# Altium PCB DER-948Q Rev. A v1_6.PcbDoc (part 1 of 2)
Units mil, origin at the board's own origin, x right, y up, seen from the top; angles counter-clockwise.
Board outline 4950 x 2915 mil, 6 copper layers (Top Layer, Mid-Layer 1, Mid-Layer 2, Mid-Layer 3, Mid-Layer 4, Bottom Layer), stack 69.8 mil thick; 98 components, 37 nets, 247 pads, 846 vias.
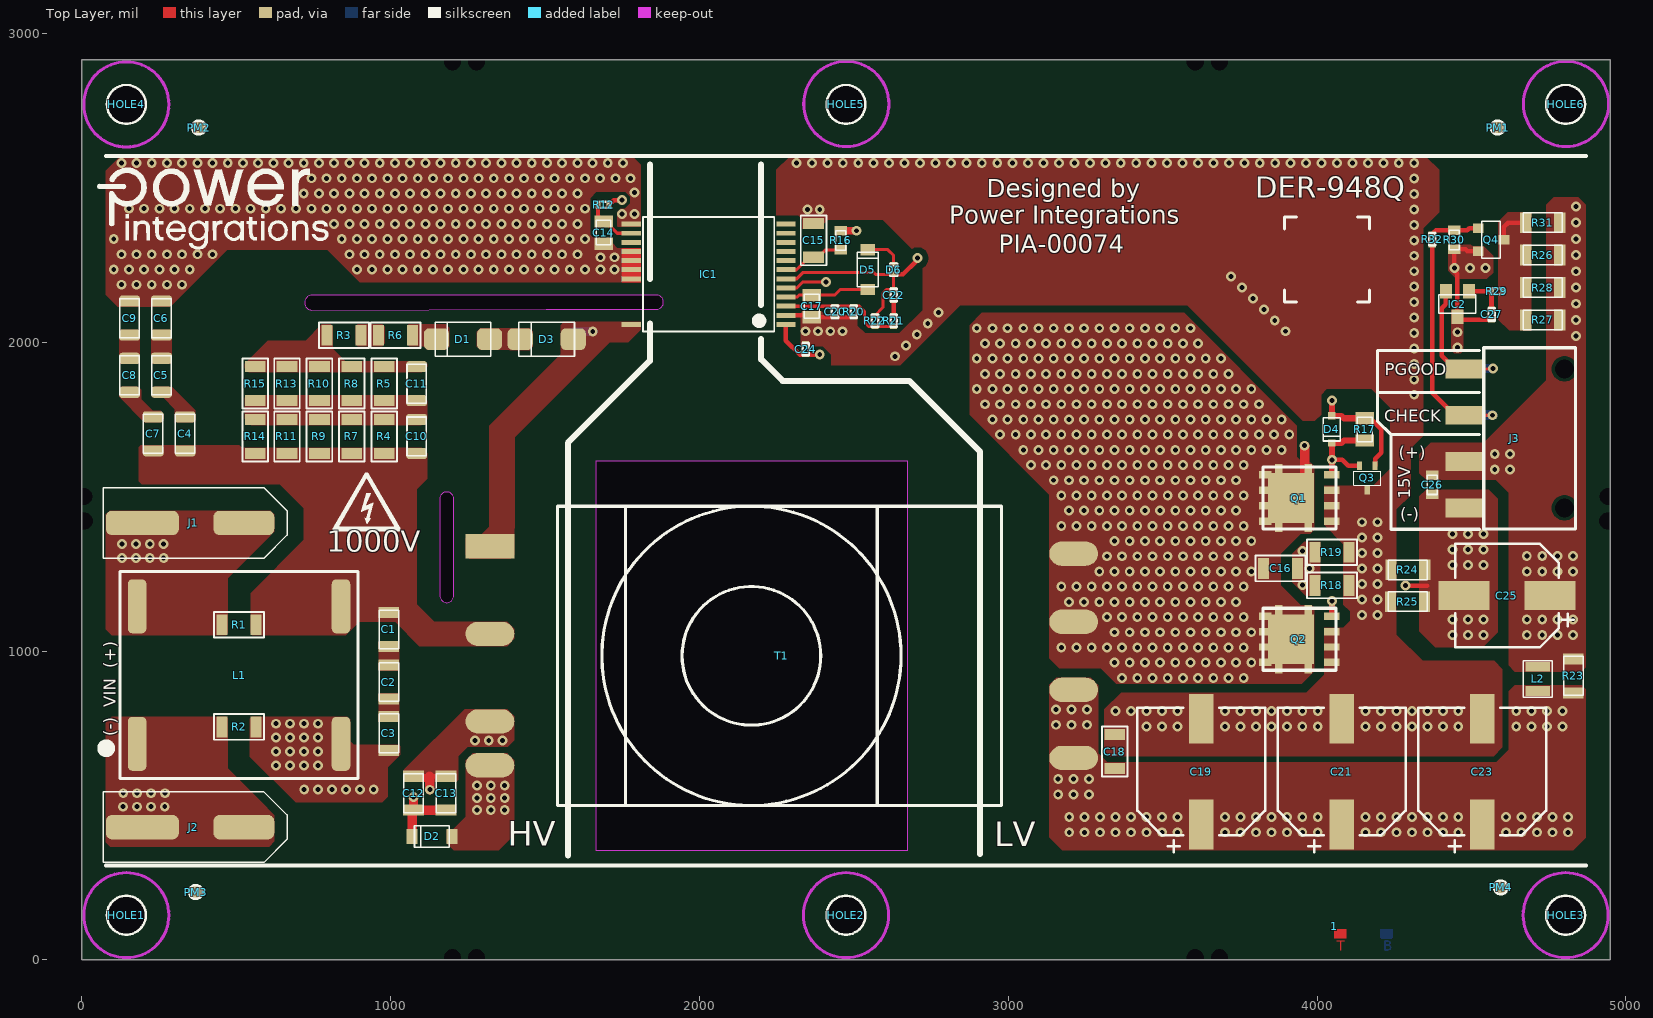
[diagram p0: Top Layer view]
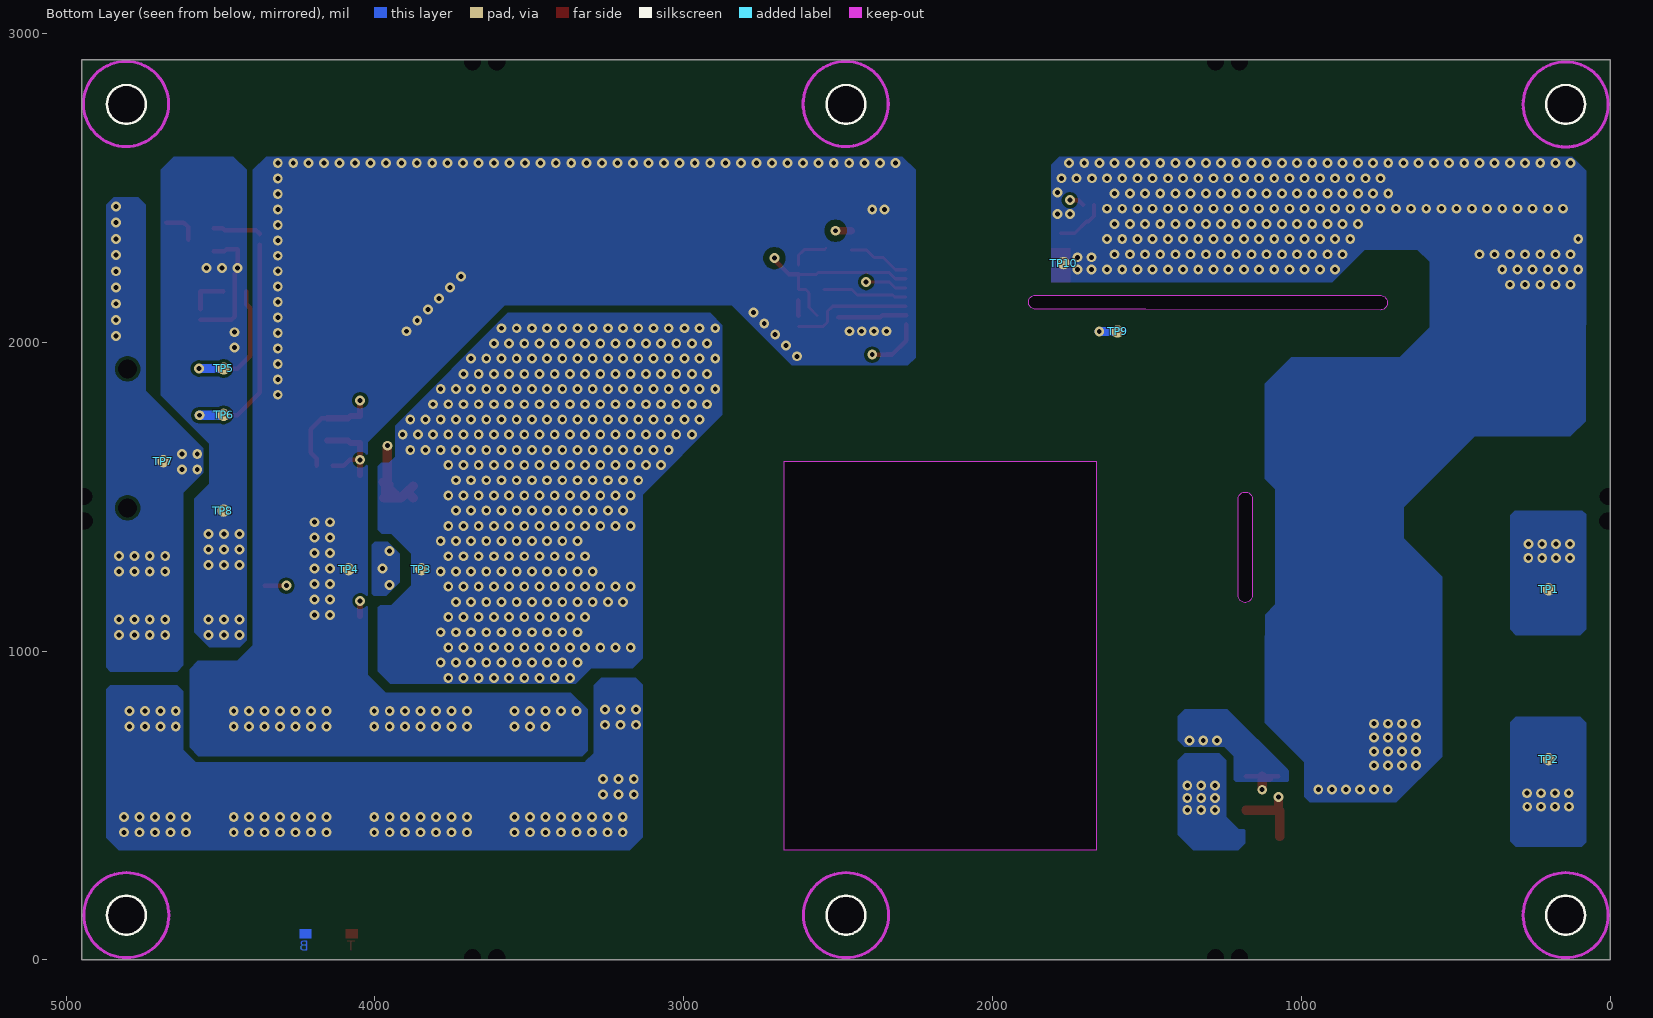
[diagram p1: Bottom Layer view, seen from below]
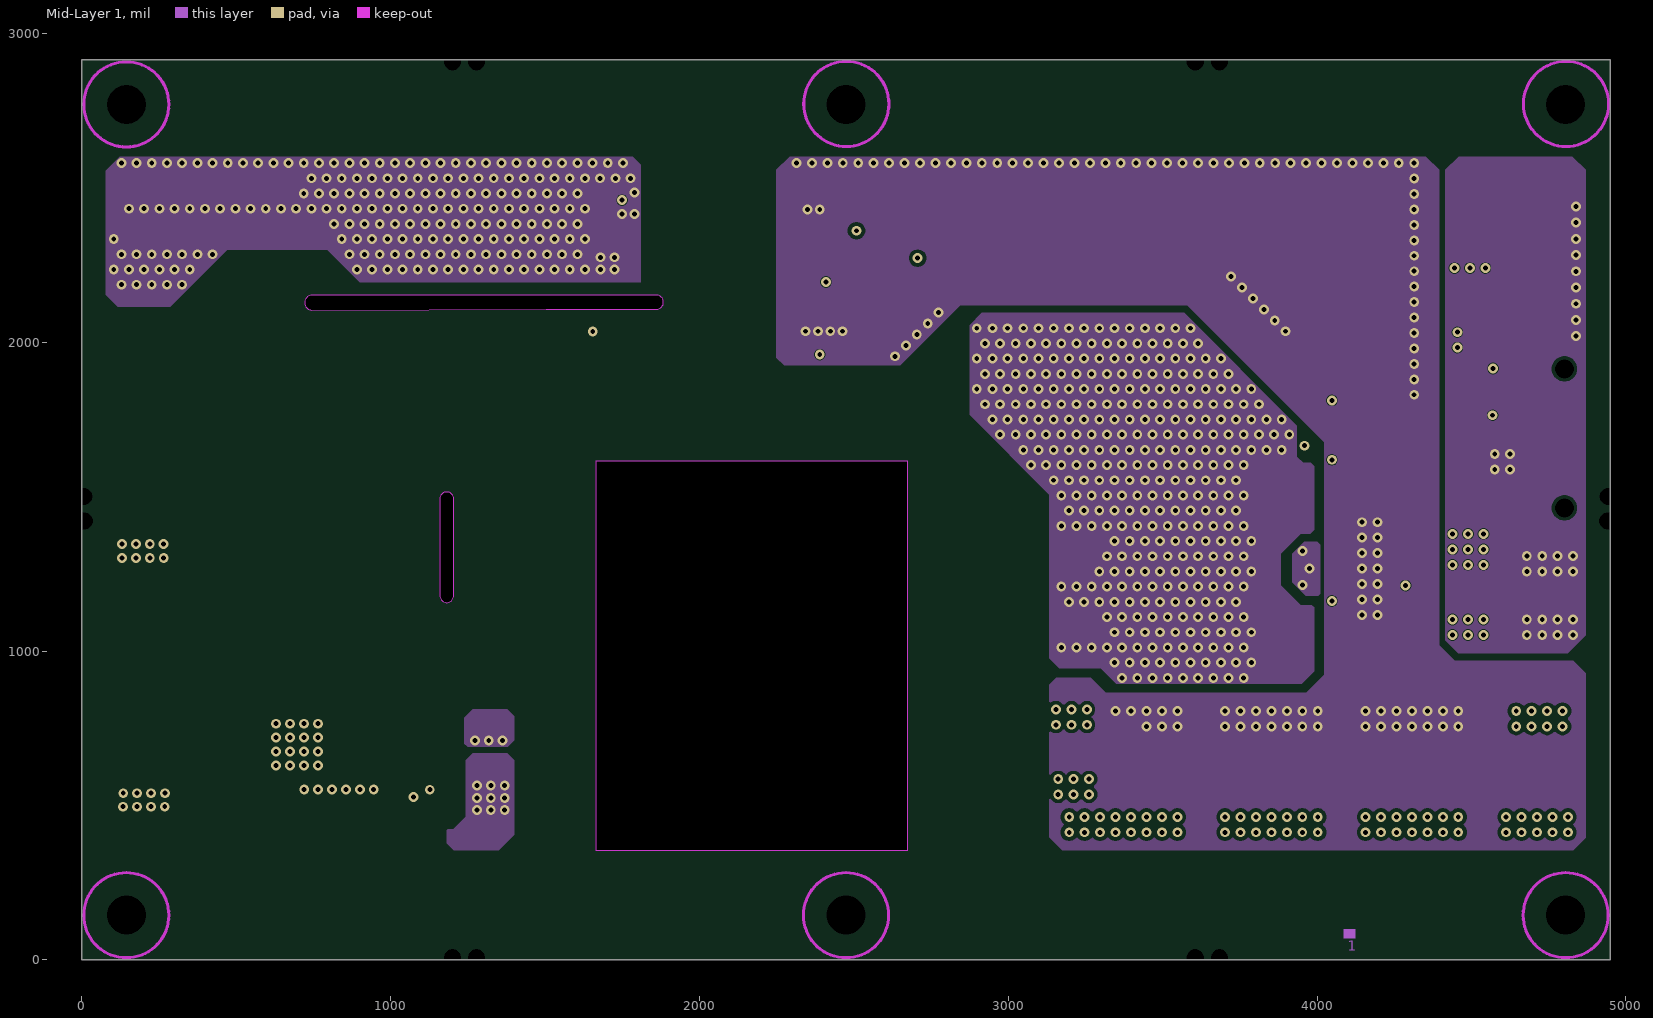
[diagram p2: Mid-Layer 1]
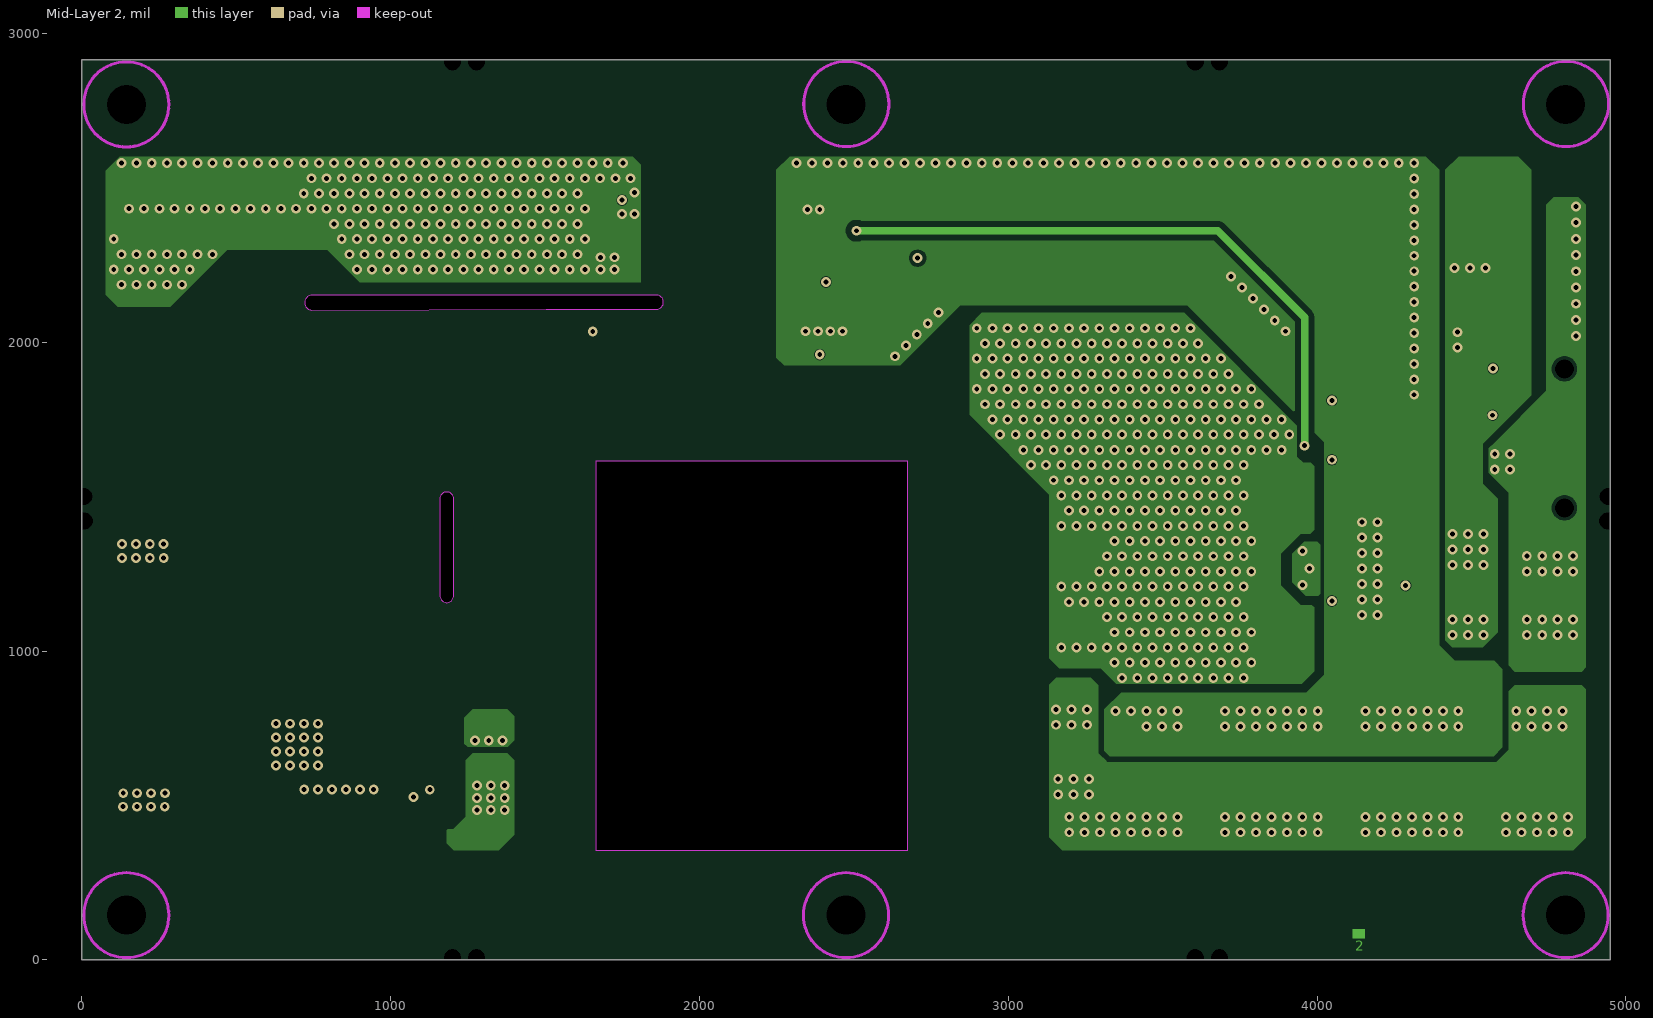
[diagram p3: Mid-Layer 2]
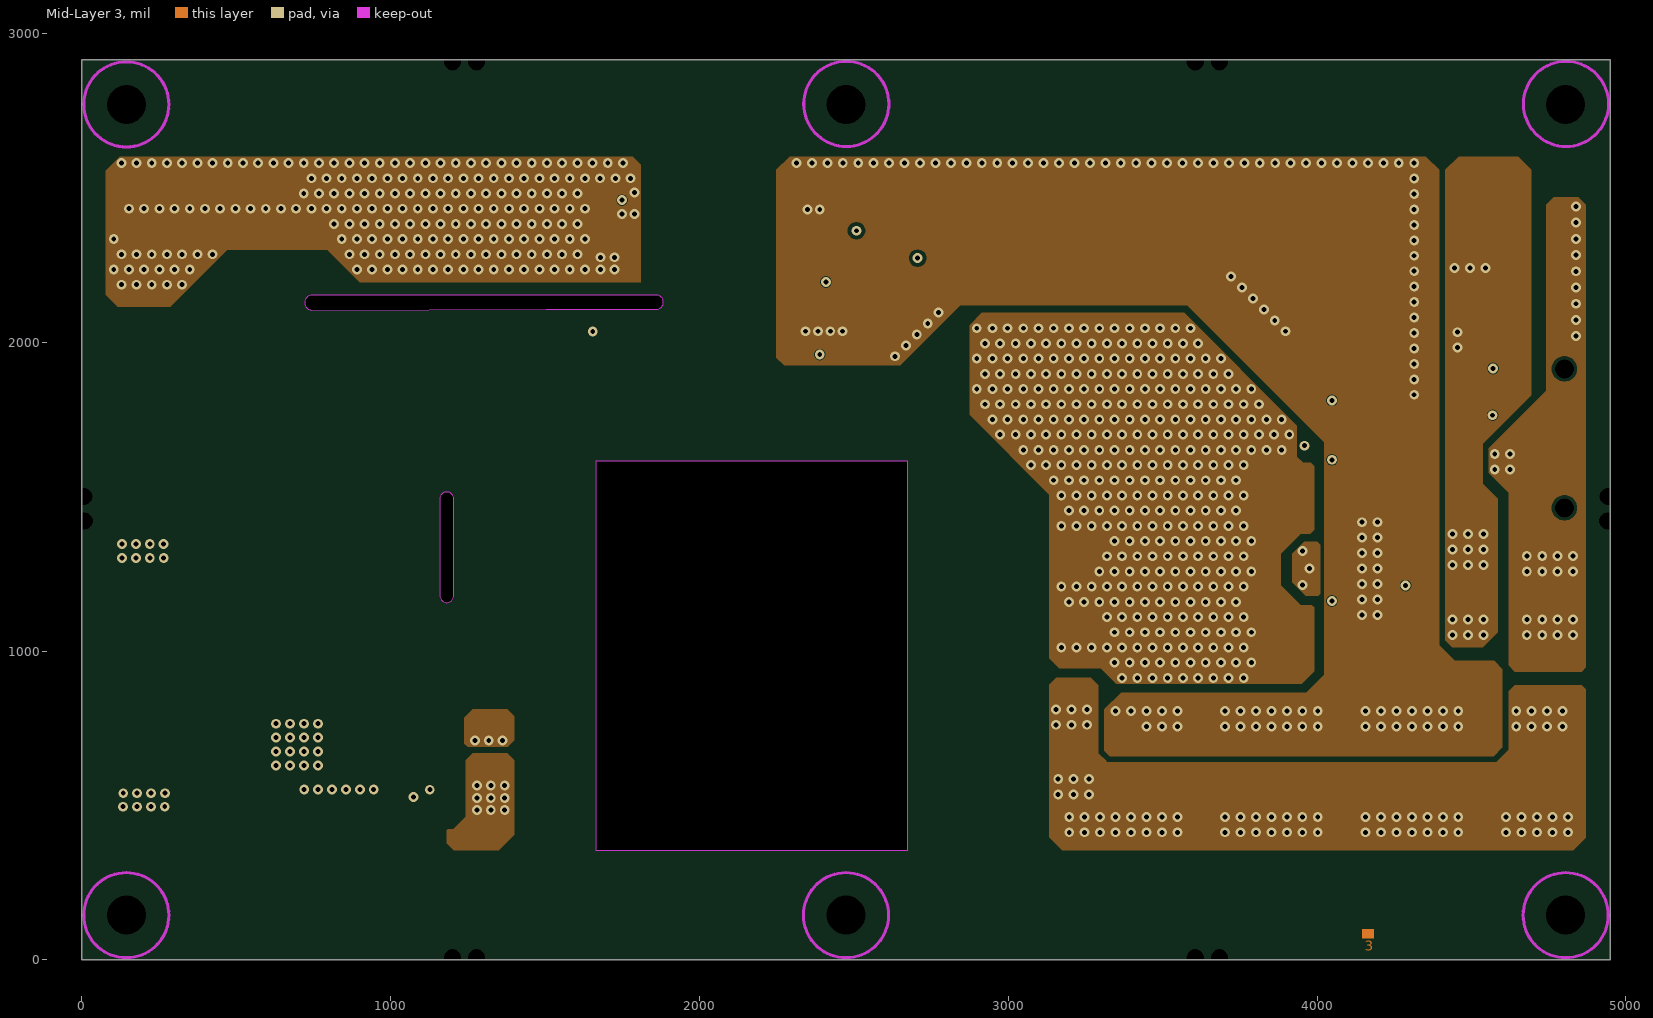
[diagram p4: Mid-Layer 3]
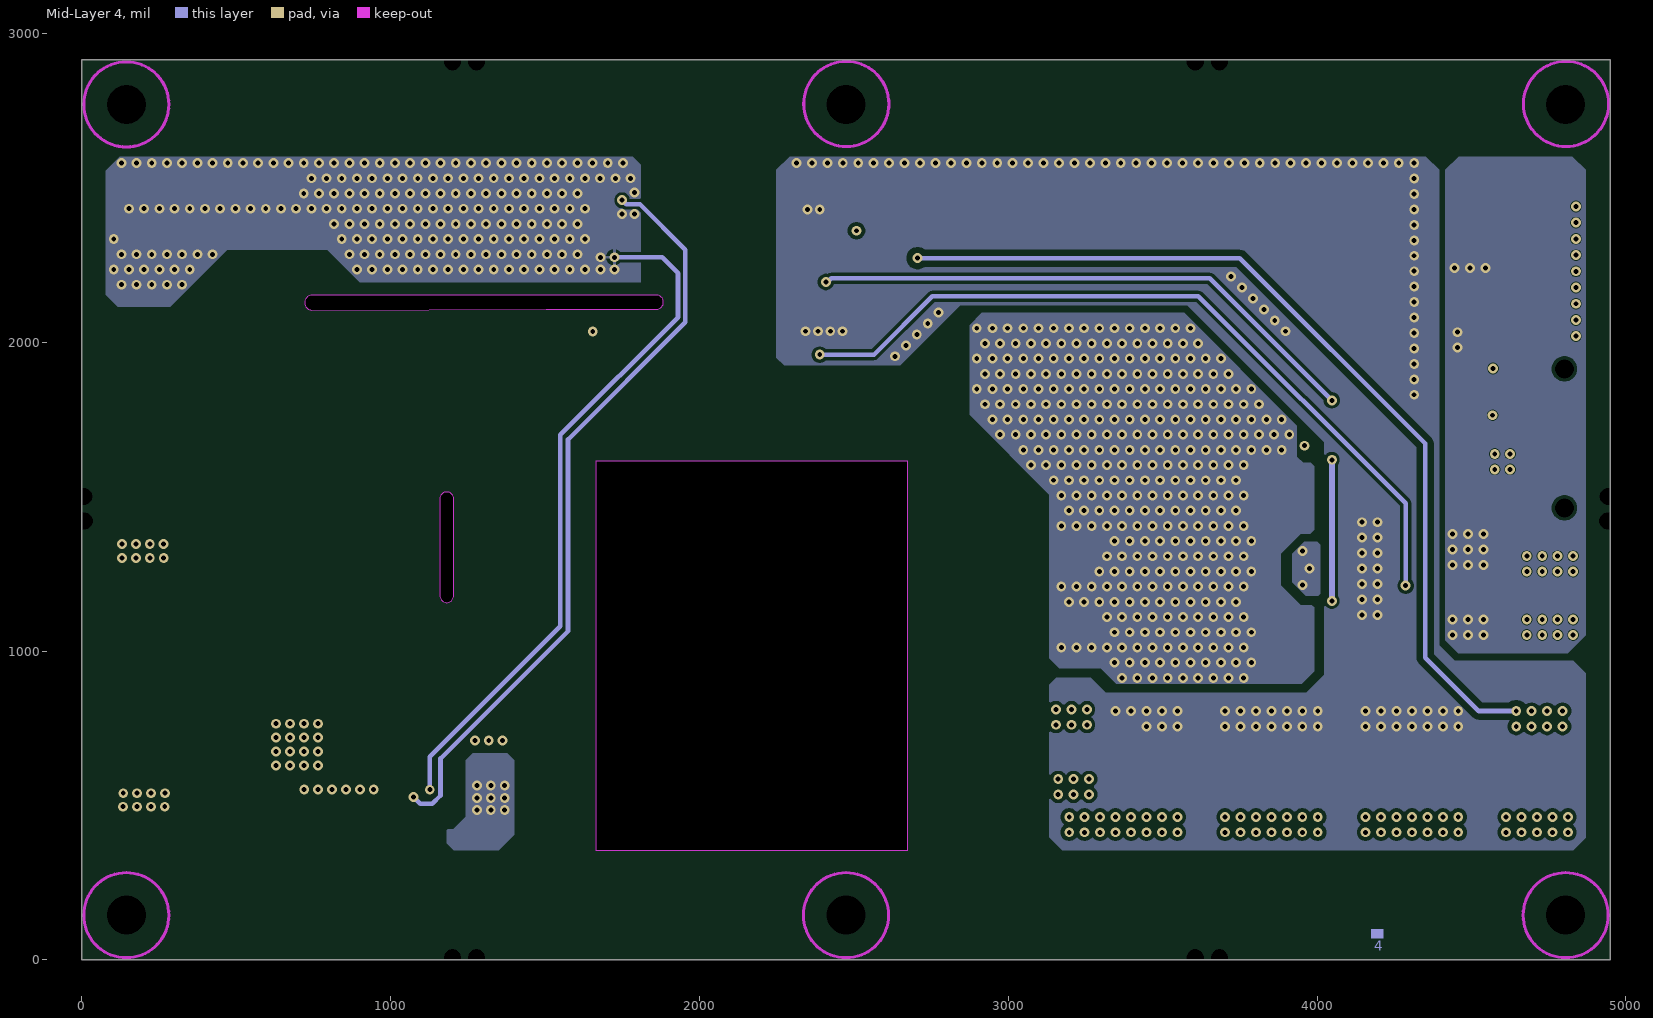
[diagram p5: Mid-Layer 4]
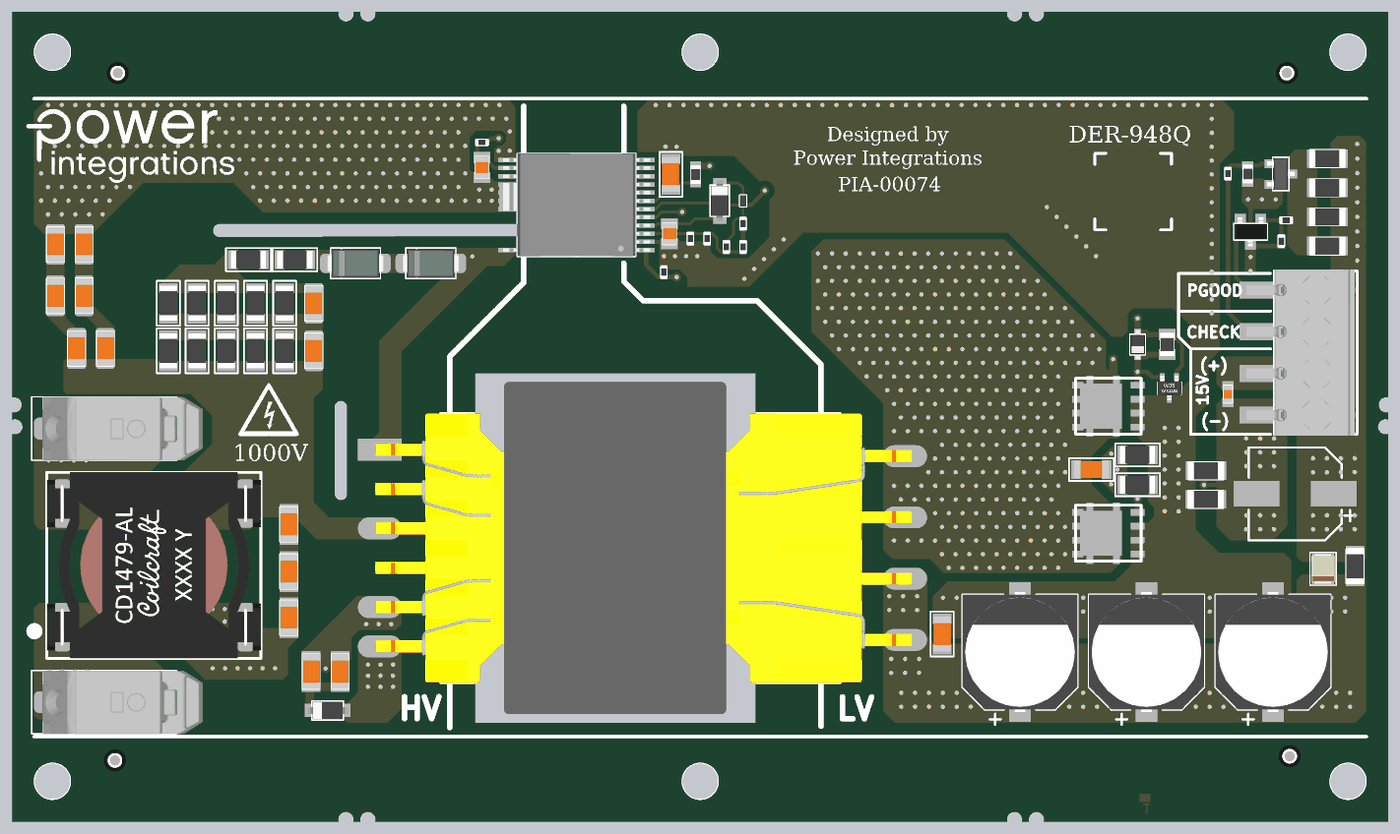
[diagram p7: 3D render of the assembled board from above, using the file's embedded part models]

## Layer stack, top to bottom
Top Solder: solder mask 0.3941, GL 2467 SG-DG, Dk 3.5
Top Layer: signal copper 1.4
Dielectric 1: core 14.2, Core-R-1566W, Dk 4.5
Mid-Layer 1: signal copper 1.4
Dielectric 10: prepreg 2, PP-106, Dk 4.1
Dielectric 2: prepreg 2, PP-106, Dk 4.1
Mid-Layer 2: signal copper 1.4
Dielectric 3: prepreg 2.7, PP-1080, Dk 4.1
Dielectric 4: prepreg 2.7, PP-1080, Dk 4.1
Dielectric 5: core 14.2, Core-R-1566W, Dk 4.7
Dielectric 11: prepreg 2.7, PP-1080, Dk 4.1
Dielectric 6: prepreg 2.7, PP-1080, Dk 4.1
Mid-Layer 3: signal copper 1.4
Dielectric 13: prepreg 2, PP-106, Dk 4.1
Dielectric 12: prepreg 2, PP-106, Dk 4.1
Mid-Layer 4: signal copper 1.4
Dielectric 7: core 14.2, Core-R-1566W, Dk 4.5
Bottom Layer: signal copper 1.4
Bottom Solder: solder mask 0.3941, GL 2467 SG-DG, Dk 3.5

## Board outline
0,2915 0,0 4950,0 4950,2915
cut-out: 745.99,2104.28 1505.02,2106.86 1861.5,2106.86 ccw(c1861.5,2129.5) 1859,2152 746,2152 ccw(c745.91,2128.14)
cut-out: 1205.07,1179.87 1205,1200 1205,1489.87 ccw(c1182.5,1492.37) 1160,1489.87 1160,1179.87 ccw(c1182.53,1179.8)
cut-out: 1665,355 2675,355 2675,1615 1665,1615

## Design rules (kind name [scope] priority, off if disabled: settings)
AcuteAngle [All] p1: minimum=9.00000000000000E+0001 checktracksonly=FALSE
BoardOutlineClearance BoardOutlineClearance_1 [InComponent('IC1')] p1: gap=0 ignorepadtopadclearanceinfootprint=FALSE
BoardOutlineClearance Mousebites [InNamedUnion('Mousebites')] p2: gap=0 ignorepadtopadclearanceinfootprint=FALSE
BoardOutlineClearance T1 [InComponent('T1')] p3: gap=0 ignorepadtopadclearanceinfootprint=FALSE
BoardOutlineClearance [All] p4: gap=35 ignorepadtopadclearanceinfootprint=FALSE except(0: Text-OutlineEdge Text-CutoutEdge)
Clearance "Clearance HV+ wrt Bias/Source" [InNet('HV+ (1000 V)') vs InNet('Source') OR InNet('NetC6_1')] p1: gap=94.49 ignorepadtopadclearanceinfootprint=FALSE
Clearance "Clearance 15V wrt GND/IS" [InNet('GND') OR InNet('IS') vs InNet('SEC_TRF+') OR InNet('15VCC (+)')] p2: gap=19.68 ignorepadtopadclearanceinfootprint=FALSE
Clearance "Clearance Dsnub2/Vsnub2 wrt DRAIN" [InNet('VSNUB2') OR InNet('DSnub2') vs InNet('DRAIN')] p3: gap=70.87 ignorepadtopadclearanceinfootprint=FALSE
Clearance "Clearance Dsnub2/Vsnub2 wrt Dsnub1" [InNet('VSNUB2') OR InNet('Dsnub2') vs InNet('Dsnub1')] p4: gap=23.62 ignorepadtopadclearanceinfootprint=FALSE
Clearance "Clearance Q1_D wrt SGND u RTN" [InNet('Q1_D') vs InNet('GND') OR InNet('IS')] p5: gap=19.68 ignorepadtopadclearanceinfootprint=FALSE
Clearance "Clearance 15V wrt Q1_D" [InNet('SEC_TRF+') OR InNet('15VCC (+)') vs InNet('Q1_D')] p6: gap=19.68 ignorepadtopadclearanceinfootprint=FALSE
Clearance "Clearance BIAS wrt Source" [InNet('NetC8_1') OR InNet('NetD3_A') vs InNet('SOURCE')] p7: gap=13.78 ignorepadtopadclearanceinfootprint=TRUE except(0: Arc-Hole Track-Hole SMDPad-Hole THPad-Hole Via-Hole Fill-Hole Poly-Hole Region-Hole Text-Hole)
Clearance "Clearance Drain wrt AUX" [InNet('DRAIN') vs InNet('SOURCE') OR InNet('NetD3_A') OR InNet('NetC8_1')] p8: gap=94.49 ignorepadtopadclearanceinfootprint=TRUE
Clearance "Clearance Drain wrt HV_TRF" [InNet('DRAIN') vs InNet('HV_TRF')] p9: gap=94.49 ignorepadtopadclearanceinfootprint=FALSE
Clearance "Clearance NetD1_A wrt Drain" [InNet('Dsnub2') vs InNet('DRAIN')] p10: gap=23.62 ignorepadtopadclearanceinfootprint=FALSE
Clearance "Clearance NetD1_K wrt HV_TRF" [InNet('Dsnub1') vs InNet('HV_TRF')] p11: gap=47.24 ignorepadtopadclearanceinfootprint=FALSE
Clearance "Clearance Vsnub2 wrt HV_TRF" [InNet('VSNUB2') vs InNet('HV_TRF')] p12: gap=59.06 ignorepadtopadclearanceinfootprint=FALSE
Clearance "Clearance Vsnub1 wrt HV_TRF" [InNet('VSNUB1') vs InNet('HV_TRF')] p13: gap=15.75 ignorepadtopadclearanceinfootprint=FALSE
Clearance "Clearance Drain NETC1_2" [InNet('DRAIN') vs InNet('NetC1_2')] p14: gap=94.49 ignorepadtopadclearanceinfootprint=FALSE
Clearance "Clearance Drain NETC2_2" [InNet('DRAIN') vs InNet('NetC2_2')] p15: gap=94.49 ignorepadtopadclearanceinfootprint=FALSE
Clearance "Clearance C2 wrt Source" [InNet('NetC1_2') vs InNet('SOURCE')] p16: gap=141.73 ignorepadtopadclearanceinfootprint=FALSE
Clearance "Clearance C3 wrt Source" [InNet('NetC2_2') vs InNet('SOURCE')] p17: gap=70.87 ignorepadtopadclearanceinfootprint=FALSE
Clearance "Clearance prim wrt sec" [InNetClass('Primary Side') vs InNetClass('Secondary Side 1')] p18: gap=188.98 ignorepadtopadclearanceinfootprint=FALSE
Clearance "Clearance HV_TRF wrt Source" [InNet('HV_TRF') vs InNet('SOURCE') OR InNet('NetD3_A')] p19: gap=94.49 ignorepadtopadclearanceinfootprint=FALSE
Clearance "Clearance HV+ wrt HV-" [InNet('HV+ (1000 V)') vs InNet('HV-')] p20: gap=94.49 ignorepadtopadclearanceinfootprint=FALSE
Clearance Clearance_Pri_Vin-Drain [InNet('HV_TRF') vs InNet('DRAIN')] p21: gap=16.14 ignorepadtopadclearanceinfootprint=FALSE except(0: Arc-Hole Track-Hole SMDPad-Hole THPad-Hole Via-Hole Fill-Hole Poly-Hole Region-Hole Text-Hole)
Clearance Clearance_Domains_Pri-Sec [InNetClass('Primary Side') vs InNetClass('Secondary Side 1')] p22: gap=342.52 ignorepadtopadclearanceinfootprint=FALSE except(0: Arc-Hole Track-Hole SMDPad-Hole THPad-Hole Via-Hole Fill-Hole Poly-Hole Region-Hole Text-Hole)
Clearance Clearance_D-S [InNet('DRAIN') vs InNet('SOURCE')] p23: gap=39.37 ignorepadtopadclearanceinfootprint=FALSE except(0: Arc-Hole Track-Hole SMDPad-Hole THPad-Hole Via-Hole Fill-Hole Poly-Hole Region-Hole Text-Hole)
Clearance Clearance_VIA-PAD [IsVia vs IsPad AND NOT InComponent ('PM*')] p24: gap=1 ignorepadtopadclearanceinfootprint=FALSE except(0: Arc-Hole Track-Hole SMDPad-Hole THPad-Hole Via-Hole Fill-Hole Poly-Hole Region-Hole Text-Hole)
Clearance Clearance_TP [InComponent('TP*') vs InComponent('TP*')] p25: gap=40 ignorepadtopadclearanceinfootprint=FALSE except(0: Arc-Hole Track-Hole SMDPad-Hole THPad-Hole Via-Hole Fill-Hole Poly-Hole Region-Hole Text-Hole) // TP to TP
Clearance Clearance_Polygon [InPolygon] p26: gap=10 ignorepadtopadclearanceinfootprint=FALSE except(0: Arc-Hole Track-Hole SMDPad-Hole THPad-Hole Via-Hole Fill-Hole Poly-Hole Region-Hole Text-Hole)
Clearance Clearance_Layer-Set [InComponent('*Layer')] p27: gap=5 ignorepadtopadclearanceinfootprint=FALSE except(0: Arc-Hole Track-Hole SMDPad-Hole THPad-Hole Via-Hole Fill-Hole Poly-Hole Region-Hole Text-Hole) // whole Board
Clearance Clearance_All [All] p28: gap=8 ignorepadtopadclearanceinfootprint=FALSE except(0: Arc-Hole Track-Hole SMDPad-Hole THPad-Hole Via-Hole Fill-Hole Poly-Hole Region-Hole Text-Hole) // whole Board
ComponentClearance [All] p1: gap=40 collisioncheckmode=3 verticalgap=10 showdistances=FALSE donotcheckwithout3dbody=TRUE
Creepage "Creepage Dsnub1/2 wrt Source" [InNet('Dsnub1') OR InNet('Dsnub2') vs InNet('SOURCE')] p1: checkdistance=259.84
Creepage "Creepage HV+ wrt BIAS/Source" [InNet('HV+ (1000 V)') vs InNet('Source') OR InNet('NetC6_1')] p2: checkdistance=196.85
Creepage "Creepage_NetD3_A wrt SOURCE" [InNet('NetD3_A') vs InNet('SOURCE')] p3: checkdistance=19.68 ignoreinternallayers=FALSE
Creepage "Creepage Dsnub2/Vsnub2 wrt DRAIN" [InNet('VSNUB2') OR InNet('Dsnub2') vs InNet('DRAIN')] p4: checkdistance=141.73 ignoreinternallayers=FALSE
Creepage "Creepage Dsnub2/Vsnub2 wrt Dsnub1" [InNet('VSNUB2') OR InNet('Dsnub2') vs InNet('Dsnub1')] p5: checkdistance=74.8 ignoreinternallayers=FALSE
Creepage "Creepage Vsnub2 wrt SOURCE" [InNet('VSNUB2') vs InNet('SOURCE')] p6: checkdistance=259.84 ignoreinternallayers=FALSE
Creepage "Creepage Q1_D wrt SGND u RTN" [InNet('Q1_D') vs InNet('GND') OR InNet('IS')] p7: checkdistance=19.68
Creepage "Creepage 15V wrt Q1_D" [InNet('SEC_TRF+') OR InNet('15VCC (+)') vs InNet('Q1_D')] p8: checkdistance=19.68 ignoreinternallayers=FALSE
Creepage "Creepage BIAS wrt Source" [InNet('NetC8_1') OR InNet('NetD3_A') vs InNet('SOURCE')] p9: checkdistance=13.78 ignoreinternallayers=FALSE
Creepage "Creepage Drain wrt AUX" [InNet('DRAIN') vs InNet('SOURCE') OR InNet('NetD3_A') OR InNet('NetC8_1')] p10: checkdistance=196.85
Creepage "Creepage Drain wrt HV_TRF" [InNet('DRAIN') vs InNet('HV_TRF')] p11: checkdistance=196.85 ignoreinternallayers=FALSE
Creepage "Creepage NetD1_A wrt Drain" [InNet('NetD1_A') vs InNet('DRAIN')] p12: checkdistance=70.87 ignoreinternallayers=FALSE
Creepage "Creepage NetD1_K wrt Source" [InNet('NetD1_K') vs InNet('SOURCE')] p13: checkdistance=259.84 ignoreinternallayers=FALSE
Creepage "Creepage NetD1_K wrt HV_TRF" [InNet('NetD1_K') vs InNet('HV_TRF')] p14: checkdistance=106.3 ignoreinternallayers=FALSE
Creepage "Creepage Vsnub2 wrt HV_TRF" [InNet('VSNUB2') vs InNet('HV_TRF')] p15: checkdistance=118.11 ignoreinternallayers=FALSE
Creepage "Creepage Vsnub1 wrt HV_TRF" [InNet('VSNUB1') vs InNet('HV_TRF')] p16: checkdistance=62.99 ignoreinternallayers=FALSE
Creepage "Creepage Drain NETC1_2" [InNet('DRAIN') vs InNet('NetC1_2')] p17: checkdistance=196.85 ignoreinternallayers=FALSE
Creepage "Creepage Drain NETC2_2" [InNet('DRAIN') vs InNet('NetC2_2')] p18: checkdistance=196.85 ignoreinternallayers=FALSE
Creepage "Creepage C2 wrt Source" [InNet('NetC1_2') vs InNet('SOURCE')] p19: checkdistance=141.73 ignoreinternallayers=FALSE
Creepage "Creepage C3 wrt Source" [InNet('NetC2_2') vs InNet('SOURCE')] p20: checkdistance=70.87 ignoreinternallayers=FALSE
Creepage "Creepage HV_TRF wrt Source" [InNet('HV_TRF') vs InNet('SOURCE') OR InNet('NetD3_A')] p21: checkdistance=196.85 ignoreinternallayers=FALSE
Creepage "Creepage i prim wrt sec" [InNetClass('Primary Side') vs InNetClass('Secondary Side 1')] p22: checkdistance=251.97 ignoreinternallayers=FALSE // Inner Layers
Creepage "Creepage i HV_TRF wrt Source" [InNet('HV_TRF') vs InNet('SOURCE')] p23: checkdistance=125.98 ignoreinternallayers=FALSE // Inner Layers
Creepage "Creepage i HV+ wrt HV-" [InNet('HV+ (1000 V)') vs InNet('HV-')] p24: checkdistance=125.98 ignoreinternallayers=FALSE // Inner Layers
Creepage "Creepage prim wrt sec" [InNetClass('Primary Side') vs InNetClass('Secondary Side 1')] p25: checkdistance=393.7
Creepage "Creepage HV+ wrt HV-" [InNet('HV+ (1000 V)') vs InNet('HV-')] p26: checkdistance=196.85
Creepage Creepage_Domains_Pri-Sec [InNetClass('Primary Side') vs InNetClass('Secondary Side 1')] p27: checkdistance=393.7 ignoreinternallayers=FALSE
Creepage "Creepage_Snubber diode_1" [InNet('NetD1_A') vs InNet('NetD1_K')] p28: checkdistance=72.83
Creepage "Creepage_Snubber diode_2" [InNet('NetD1_A') vs InNet('DRAIN')] p29: checkdistance=72.83
Creepage "Creepage_Snubber diode_3" [InNet('NetD1_K') vs InNet('DRAIN')] p30: checkdistance=146.06
Creepage Creepage_Snubber_1 [InNet('HV_TRF') vs InNet('VSNUB1')] p31: checkdistance=61.81
Creepage Creepage_Snubber_2 [InNet('VSNUB1') vs InNet('VSNUB2')] p32: checkdistance=61.81
Creepage Creepage_Snubber_3 [InNet('HV_TRF') vs InNet('VSNUB2')] p33: checkdistance=118.11
Creepage Creepage_FWD-GND [InNet('FWD') vs InNet('GND')] p34: checkdistance=59.45
Creepage [All] p35: checkdistance=10
HoleSize [All] p1: absolutevalues=TRUE maxlimit=125.98 minlimit=16 maxpercent=80.000 minpercent=20.000
MinimumAnnularRing [All] p1: minimumring=8
PasteMaskExpansion PasteMaskExpansion_TP [InComponent('TP*')] p1: expansion=-100 // cover TP
PasteMaskExpansion PasteMaskExpansion_All [All] p2: expansion=0
PolygonConnect PolygonConnect_All [All] p1: connectstyle=Direct reliefconductorwidth=10 reliefentries=4 polygonreliefangle="90 Angle" airgapwidth=10 // Full Connect
RoutingVias [All] p1: holewidth=16 width=32 viastyle="Through Hole" minholewidth=16 minwidth=32 maxholewidth=16 maxwidth=32
SilkToSolderMaskClearance SilkscreenOverComponentPads [IsPad] p1: minsilkscreentomaskgap=10 clearancetoexposedcopper=TRUE
SolderMaskExpansion SolderMaskExpansion_PM [InComponent('PM*')] p1: expansion=19.68 istentingtop=FALSE // 1mm
SolderMaskExpansion SolderMaskExpansion_VIA [(IsVia)] p2: expansion=-8 istentingtop=FALSE // cove copper
SolderMaskExpansion SolderMaskExpansion_All [All] p3 off: expansion=0 istentingtop=FALSE
Width [All] p1: maxlimit=100 minlimit=10 preferedwidth=10
26 further rules are at their usual default settings.

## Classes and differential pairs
net class "Secondary Side 1": "15VCC (+)" "15VCC (-)" CHECK FWD GND NetC16_2 NetC17_1 NetC20_2 NetC22_2 NetC27_2 NetD4_K NetD5_K NetQ4_D NetQ4_G PGOOD Q1_D SEC_TRF+ SR
net class "Primary Side": DRAIN Dsnub1 Dsnub2 "HV+ (1000 V)" HV- HV_TRF NetC1_2 NetC2_2 NetC4_2 NetC5_2 NetC7_2 NetC8_2 NetC12_1 NetC14_1 NetD2_A NetIC1_8 NetIC1_9 NetIC1_10 NetIC1_11 NetIC1_12 NetIC1_15 NetJ1_2 NetJ1_3 NetJ1_4 NetR3_2 SOURCE VSNUB1 VSNUB2

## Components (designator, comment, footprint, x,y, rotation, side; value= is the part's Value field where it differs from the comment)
1 "6-Layer" PCB_6-LAYER 4055,110 r0 top
C1 "68n" CT_1206_C_RS#1 995,1070 r270 top
C2 "68n" CT_1206_C_RS#1 995,900 r270 top
C3 "68n" CT_1206_C_RS#1 995,733.79 r270 top
C4 "68n" CT_1206_C_RS#2 335.28,1703.4 r90 top
C5 "68n" CT_1206_C_RS#2 258.87,1893.18 r90 top
C6 "68n" CT_1206_C_RS#2 258.87,2077.92 r90 top
C7 "68n" CT_1206_C_RS#2 231.91,1703.4 r90 top
C8 "68n" CT_1206_C_RS#2 155.5,1893 r90 top
C9 "68n" CT_1206_C_RS#2 155.5,2077.93 r90 top
C10 "6n8" CT_1206_C_RS#2 1085.18,1695 r90 top
C11 "6n8" CT_1206_C_RS#2 1085.18,1866 r90 top
C12 "10u" CT_1206_C_RS#1 1075,540 r90 top
C13 "10u" CT_1206_C_RS#1 1180,540 r90 top
C14 "4u7" CT_0805_C_RS 1690,2355 r270 top
C15 "330p" ATV_1206_C_RS 2370,2330 r270 top
C16 "1500p" ATV_1206_C_RS 3882,1267.73 r0 top
C17 "2u2" CT_0805_C_RS 2364.11,2116.65 r270 top
C18 "470n" ATV_1206_C_RS 3345,675 r90 top
C19 "470u" CAPAE10x12p5L_B40900 3625,610 r90 top
C20 "330p" ATV_0402_C 2439.45,2098.94 r90 top
C21 "470u" CAPAE10x12p5L_B40900 4080,610 r90 top
C22 "10n" ATV_0402_C 2629.09,2152.95 r270 top
C23 "470u" CAPAE10x12p5L_B40900 4535,610 r90 top
C24 "330p" ATV_0402_C 2344.11,1977.72 r270 top
C25 "N.A." CAPAE8x10L_GYC 4615,1180 r180 top
C26 "100n" CT_0603_C_RS 4373.1,1538.61 r270 top
C27 "10n" ATV_0402_C 4565,2090 r90 top
D1 "NRVUS2MA" CT_DIODE_SMA_RS 1235,2010 r0 top
D2 "BAS21GWX" CT_SOD123_RS 1135,400 r0 top
D3 "NRVUS2MA" CT_DIODE_SMA_RS 1505.96,2010 r0 top
D4 "N.A." CT_SOD323_RS 4047.99,1717.67 r0 top
D5 "PDZ15BGWJ" CT_SOD123_RS 2545.37,2235 r270 top
D6 "SBR0240LPW-7B" CT_DIODE_X1-DFN1006-2_RS 2629.09,2235 r270 top
HOLE1 "HOLE-3.2mm" PCB_HOLE-3.2 145,145 r0 top
HOLE2 "HOLE-3.2mm" PCB_HOLE-3.2 2475,145 r0 top
HOLE3 "HOLE-3.2mm" PCB_HOLE-3.2 4805,145 r0 top
HOLE4 "HOLE-3.2mm" PCB_HOLE-3.2 145,2770 r0 top
HOLE5 "HOLE-3.2mm" PCB_HOLE-3.2 2475,2770 r90 top
HOLE6 "HOLE-3.2mm" PCB_HOLE-3.2 4805,2770 r90 top
IC1 "INN3949CQ" ATV_InSOP-24D 2030,2220 r180 top
IC2 "TL431MFDT,215" CT_SOT23_RS 4454.3,2123.47 r180 top
J1 "SR99S01VBNN04G7" ATV_METZ_SM99S01VB 505.87,1415 r180 top
J2 "SM99S01VBNN00G7" ATV_METZ_SM99S01VB 505.87,430 r180 top locked
J3 "2383945-4" ATV_TE_2383945-4 4638.62,1688.61 r90 top locked
L1 "590uH" ATV_CD1479-ALD 510,922.5 r90 top
L2 "N.A." CT_IND_1008_RS 4715,910 r90 top
PM1 "FIDUCIAL" PCB_FIDUCIAL 4585,2695 r0 top
PM2 "FIDUCIAL" PCB_FIDUCIAL 380,2695 r0 top
PM3 "FIDUCIAL" PCB_FIDUCIAL 370,220 r0 top
PM4 "FIDUCIAL" PCB_FIDUCIAL 4595,235 r0 top
Q1 "DMT15H017LPS-13" CT_PowerDI5060-8_RS 3942.87,1495.53 r90 top
Q2 "DMT15H017LPS-13" CT_PowerDI5060-8_RS 3942.87,1038.32 r90 top
Q3 "N.A." ATV_SOT323_FET_P 4162.49,1560.52 r180 top
Q4 "NX3008NBK,215" ATV_SOT23_FET 4563.31,2331.64 r270 top
R1 "N.A." ATV_1206_R_RS 510.08,1085.32 r0 top
R2 "N.A." ATV_1206_R_RS 510.08,754.57 r0 top
R3 "7R5" ATV_1206_R_RS 850,2023 r0 top
R4 "390K" ATV_1206_R_RS 980.18,1695 r90 top
R5 "390K" ATV_1206_R_RS 980.18,1866 r90 top
R6 "7R5" ATV_1206_R_RS 1017,2023 r0 top
R7 "390K" ATV_1206_R_RS 875.18,1695 r90 top
R8 "390K" ATV_1206_R_RS 875.18,1866 r90 top
R9 "390K" ATV_1206_R_RS 770.18,1695 r90 top
R10 "390K" ATV_1206_R_RS 770.18,1866 r90 top
R11 "390K" ATV_1206_R_RS 665.18,1695 r90 top
R12 "8K2" ATV_0402_R 1690,2445.17 r180 top
R13 "390K" ATV_1206_R_RS 665.18,1866 r90 top
R14 "390K" ATV_1206_R_RS 562,1695 r90 top
R15 "390K" ATV_1206_R_RS 562,1866 r90 top
R16 "100R" CT_0603_R_RS 2458.18,2330 r270 top
R17 "4R7" CT_0805_R_RS 4154.48,1717.67 r90 top
R18 "12R" ATV_1206_R_RS 4048,1212.73 r0 top
R19 "12R" ATV_1206_R_RS 4048,1320 r0 top
R20 "9K1" ATV_0402_R 2499.91,2098.94 r90 top
R21 "10K" ATV_0402_R 2629,2069.02 r270 top
R22 "100K" ATV_0402_R 2568.82,2069.02 r90 top
R23 "0R" CT_1206_R_RS 4830,920 r90 top
R24 "0R027" CT_1206_R_RS 4293.91,1263.01 r0 top
R25 "0R027" CT_1206_R_RS 4293.36,1160 r0 top
R26 "1K8" CT_1206_R_RS 4730.73,2282.18 r180 top
R27 "1K8" CT_1206_R_RS 4730.73,2072.18 r180 top
R28 "1K8" CT_1206_R_RS 4730.73,2177.18 r180 top
R29 "5K6" ATV_0402_R 4582.28,2165 r180 top
R30 "2K2" CT_0603_R_RS 4444.09,2331.64 r270 top
R31 "1K8" CT_1206_R_RS 4730.73,2387.18 r180 top
R32 "4R7" ATV_0402_R 4373.1,2332.92 r90 top
T1 "TRF_EQ-30-1-L" ATV_TRF_EQ-30-1-L 2168.75,984.75 r0 top value=EIQ30-10P-SMD-35W
TP1 "ICT-100SP-BL" ICT-100SP-BL-25MIL#1 200,1200 r90 top
TP2 "ICT-100SP-BL" ICT-100SP-BL-25MIL#1 200,650 r90 top
TP3 "ICT-100SP-BL" ICT-100SP-BL-25MIL#1 3850,1265 r90 top
TP4 "ICT-100SP-BL" ICT-100SP-BL-25MIL#1 4085,1265 r90 top
TP5 "ICT-100SP-BL" ICT-100SP-BL-25MIL#2 4489.71,1915 r90 top
TP6 "ICT-100SP-BL" ICT-100SP-BL-25MIL#1 4490,1765 r90 top
TP7 "ICT-100SP-BL" ICT-100SP-BL-25MIL#1 4685,1615 r90 top
TP8 "ICT-100SP-BL" ICT-100SP-BL-25MIL#3 4495,1455 r90 top
TP9 "ICT-100SP-BL" ICT-100SP-BL-25MIL#1 1595.96,2034.96 r90 top
TP10 "ICT-100SP-BL" ICT-100SP-BL-25MIL#1 1770.54,2256.22 r90 top

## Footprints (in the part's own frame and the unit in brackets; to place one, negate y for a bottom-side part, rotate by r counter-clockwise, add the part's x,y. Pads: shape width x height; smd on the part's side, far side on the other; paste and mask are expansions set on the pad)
ATV_0402_C [mm] "Chip Capacitor, 2-Leads, Body 1.00x0.50mm, IPC Medium Density"
  rect 0.4x0.6 smd: 1(-0.45,0) 2(0.45,0)
  silkscreen extent -0.5,-0.25 0.5,0.25, body extent -0.53,-0.26 0.53,0.26, height 0.4
ATV_0402_R [mm] "Chip Resistor, 2-Leads, Body 1.00x0.50mm, IPC Medium Density"
  rect 0.4x0.6 smd: 1(-0.45,0) 2(0.45,0)
  silkscreen extent -0.5,-0.25 0.5,0.25, body extent -0.53,-0.26 0.53,0.26, height 0.4
ATV_1206_C_RS [mil]
  rect 36x67 smd: 1(-55,0) 2(55,0)
  silkscreen extent -81,-41 81,41, body extent -63,-32 63,31, height 31
ATV_1206_R_RS [mil]
  rect 36x67 smd: 1(-55,0) 2(55,0)
  silkscreen extent -81,-41 81,41, body extent -63,-31 63,32, height 24
ATV_CD1479-ALD [mil]
  rrect50% 175x60 smd: 1(-222.5,330) 2(-222.5,-330) 3(222.5,-330) 4(222.5,330)
  silkscreen extent -335,-385 335,444, body extent -335,-385 335,385, height 390
ATV_InSOP-24D [mm]
  rect 1.58x0.41 smd paste+0 mask+0: 1(-6.363,4.125) 2(-6.363,3.375) 3(-6.363,2.625) 4(-6.363,1.875) 5(-6.363,1.125) 6(-6.363,0.375) 7(-6.363,-0.375) 8(-6.363,-1.125) 9(-6.363,-1.875) 10(-6.363,-2.625) 11(-6.363,-3.375) 12(-6.363,-4.125) 13(6.363,-4.125) 14(6.363,-3.375) 15(6.363,-2.625) 16-19(6.363,-1.875) 16-19(6.363,-1.125) 16-19(6.363,-0.375) 16-19(6.363,0.375) 24(6.363,4.125)
  Top Layer region: 5.575,-2.159 5.575,0.66 7.15,0.66 7.15,-2.159
  silkscreen extent -5.4,-4.7 5.4,4.7, body extent -6.72,-4.7 6.72,4.7, height 1.7
ATV_METZ_SM99S01VB [mm]
  rrect50% 5x2 smd: 1(-0.5,0)
  rrect50% 6x2 smd: 2(7.85,0)
  silkscreen extent -4.05,-2.9 11.06,2.9, body extent -4.57,-2.88 10.11,2.92, height 6.7
ATV_SOT23_FET [mm] "SOT23 pitch 0.95mm, 1.12mm height"
  rect 0.8x0.9 smd: D(0,1.051) G(-0.95,-1.051) S(0.95,-1.051)
  silkscreen extent -1.52,-0.76 1.52,0.76, body extent -1.46,-1.27 1.46,1.27, height 1
ATV_SOT323_FET_P [mm]
  rect 0.42x0.7 smd: D(0,1) G(-0.65,-1) S(0.65,-1)
  silkscreen extent -1.1,-0.56 1.1,0.58, body extent -1.1,-1.12 1.1,1.12, height 1.1
ATV_TE_2383945-4 [mm]
  rect 1.55x3.1 smd: 1(-5.715,4.125) 2(-1.905,4.125) 3(1.905,4.125) 4(5.715,4.125)
  round 0 hole 1.55 unplated: ""(-5.715,-4.125) ""(5.715,-4.125)
  silkscreen extent -7.46,-5.05 7.46,2.51, body extent -7.62,-4.82 7.62,5.08, height 8.55
ATV_TRF_EQ-30-1-L [mm]
  rect 4x2 smd: 1(-21.5,9)
  oval 4x2 smd: 3(-21.5,1.8) 5(-21.5,-5.4) 6(-21.5,-9) 7(26.5,-8.4) 8(26.5,-2.8) 9(26.5,2.8) 10(26.5,8.4)
  silkscreen extent -15.95,-12.3 20.55,12.3, body extent -21.9,-15.2 27.1,15.2, height 11.36
CAPAE8x10L_GYC [mm]
  rect 4.2x2.35 smd: 1(-3.525,0) 2(3.525,0)
  silkscreen extent -5.51,-4.25 4.25,4.25, body extent -4.25,-4.25 4.25,4.25, height 10.8
CAPAE10x12p5L_B40900 [mm]
  rect 4.1x2 smd: 1(-4.35,0) 2(4.35,0)
  silkscreen extent -6.65,-5.25 5.25,5.25, body extent -5.5,-5.25 5.5,5.25, height 9.9
CT_0603_C_RS [mil]
  rect 31x40 smd: 1(-31,0) 2(31,0)
  silkscreen extent -31,-16 31,16, body extent -31,-16 31,15, height 20
CT_0603_R_RS [mil]
  rect 31x40 smd: 1(-31,0) 2(31,0)
  silkscreen extent -31,-16 31,16, body extent -31,-16 32,16, height 18
CT_0805_C_RS [mil]
  rect 40x60 smd: 1(-36,0) 2(36,0)
  silkscreen extent -39,-24 39,24, body extent -39,-24 39,25, height 24
CT_0805_R_RS [mil]
  rect 40x60 smd: 1(-36,0) 2(36,0)
  silkscreen extent -39,-24 39,24, body extent -39,-25 39,25, height 24
CT_1206_C_RS#1 [mil]
  rect 36x67 smd: 1(-55,0) 2(55,0)
  silkscreen extent -63,-31 63,31, body extent -63,-32 63,31, height 31
CT_1206_C_RS#2 [mil]
  rrect50% 36x67 smd: 1(-55,0) 2(55,0)
  silkscreen extent -63,-31 63,31, body extent -63,-32 63,31, height 31
CT_1206_R_RS [mil]
  rect 36x67 smd: 1(-55,0) 2(55,0)
  silkscreen extent -63,-31 63,31, body extent -63,-31 63,32, height 24
CT_DIODE_SMA_RS [mil]
  rrect50% 82x70 smd: A(86,0) K(-86,0)
  silkscreen extent -90,-55 90,55, body extent -102,-51 102,51, height 95
CT_DIODE_X1-DFN1006-2_RS [mm]
  rect 0.45x0.6 smd: A(0.391,0) K(-0.391,0)
  silkscreen extent -0.52,-0.32 0.54,0.33, body extent -0.53,-0.31 0.53,0.31, height 0.54
CT_IND_1008_RS [mm]
  rect 0.8x2 smd: 1(-1,0) 2(1,0)
  silkscreen extent -1.5,-1.2 1.5,1.2, body extent -1.35,-1.05 1.35,1.05, height 1.96
CT_PowerDI5060-8_RS [mm]
  rect 0.61x1.02 smd: D(-1.905,2.795) D(-0.635,2.795) D(0.635,2.795) D(1.905,2.795)
  rect 5.61x0.6 smd: D(0,1.69) D(0,-0.735)
  rect 4.1x3.81 smd: D(0,0.69)
  rect 0.61x1.27 smd: G(1.905,-2.67) S(-1.905,-2.67) S(-0.635,-2.67) S(0.635,-2.67)
  silkscreen extent -2.55,-3 2.55,3, body extent -2.57,-3.07 2.57,3.07, height 1.1
CT_SOD123_RS [mil]
  rect 36x48 smd: A(64.61,0) K(-64.61,0)
  silkscreen extent -57,-35 56,35, body extent -73,-32 73,31, height 50
CT_SOD323_RS [mil]
  rect 24x24 smd: A(0,44) K(0,-44)
  silkscreen extent -28,-37 28,37, body extent -26,-53 27,53, height 31
CT_SOT23_RS [mil]
  rect 39x47 smd: 1(-37,-41) 2(37,-41) 3(0,41)
  silkscreen extent -60,-30 60,30, body extent -59,-52 59,52, height 43
ICT-100SP-BL-25MIL#1 [mil]
  round 40 smd far side: 1(0,0)
  round 25 on Mech16: 2(0,0)
ICT-100SP-BL-25MIL#2 [mil]
  round 40 smd far side: 1(0,-0.29)
  round 25 on Mech16: 2(0,0)
ICT-100SP-BL-25MIL#3 [mil]
  round 40 smd far side: 1(0,5)
  round 25 on Mech16: 2(0,0)
PCB_6-LAYER [mil] "PCB-Layer-control"
  Top Layer region: 0,-10 0,-40 40,-40 40,-10
  Mid-Layer 1 region: 30,-10 30,-40 70,-40 70,-10
  Mid-Layer 2 region: 60,-10 60,-40 100,-40 100,-10
  Mid-Layer 3 region: 90,-10 90,-40 130,-40 130,-10
  Mid-Layer 4 region: 120,-10 120,-40 160,-40 160,-10
  Bottom Layer region: 150,-10 150,-40 190,-40 190,-10
PCB_FIDUCIAL [mm] "Fiducial rund ohne Anschluss"
  round 1 smd mask+0.5: 0(0,0)
  silkscreen extent -0.57,-0.57 0.57,0.57
PCB_HOLE-3.2 [mm]
  round 0 hole 3.2 unplated: 0(0,0)
  silkscreen extent -1.6,-1.6 1.6,1.6

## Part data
1: library part ATV-MISC-0011
C1 C2 C3 C4 C5 C6 C7 C8 C9: library part ATV-CAP-0230, Dielectric=X7R, Manufacturer 1=KEMET, Package=1206, Temperature Range="-55 to +125°C", Tolerance=10%, Voltage=500V
C10 C11: library part ATV-CAP-0258, Dielectric=C0G, Manufacturer 1=TDK, Package=1206, Temperature Range="-55 to +125°C", Tolerance=5%, Voltage=630V
C12 C13: library part ATV-CAP-0226, Dielectric=X7R, Manufacturer 1=TDK, Package=1206, Temperature Range="-55 to +125°C", Tolerance=10%, Voltage=50V
C14: library part ATV-CAP-0244, Dielectric=X7R, Manufacturer 1=TDK, Package=0805, Temperature Range="-55 to +125°C", Tolerance=20%, Voltage=25V
C15: library part ATV-CAP-0233, Dielectric=C0G, Manufacturer 1=TDK, Package=1206, Temperature Range="-55 to +125°C", Tolerance=5%, Voltage=630V
C16: library part ATV-CAP-0299, Dielectric=C0G, Manufacturer 1=TDK, Package=1206, Temperature Range="-55 to +125°C", Tolerance=5%, Voltage=630V
C17: library part ATV-CAP-0248, Dielectric=X7R, Manufacturer 1=KEMET, Package=0805, Temperature Range="-55 to +125°C", Tolerance=10%, Voltage=25V
C18: library part ATV-CAP-0249, Dielectric=X7R, Manufacturer 1="Taiyo Yuden", Package=1206, Temperature Range="-55 to +125°C", Tolerance=10%, Voltage=100V
C19 C21 C23: library part ATV-CAP-0250, Dielectric=AL, Manufacturer 1="EPCOS / TDK", Package=10x12.5mm, Temperature Range="-40 to +125°C", Tolerance=20%, Voltage=25V
C20 C24: library part ATV-CAP-0246, Dielectric=X7R, Manufacturer 1=Vishay, Package=0402, Temperature Range="-55 to +150°C", Tolerance=10%, Voltage=16V
C22 C27: library part ATV-CAP-0065, Dielectric=X7R, Manufacturer 1=TDK, Package=0402, Temperature Range="-55 to +125°C", Tolerance=10%, Voltage=25V
C25: library part ATV-CAP-0298, Package=8x10mm
C26: library part ATV-CAP-0239, Dielectric=X7R, Manufacturer 1=TDK, Package=0603, Temperature Range="-55 to +125°C", Tolerance=10%, Voltage=25V
D1 D3: library part ATV-DIO-0035, Current=1.5A, Forward Voltage="1.7V @ If {} 1.5A", Manufacturer 1="On Semi", Package=SMA, Reverse Voltage=1000V, Temperature Range="-55 to +150°C"
D2: library part ATV-DIO-0036, Current=200mA, Forward Voltage="1.25v @ If {} 200mA", Manufacturer 1=Nexperia, Package=SOD-123, Power=250mW, Reverse Voltage=250V, Temperature Range="-65 to +150°C"
D4: library part ATV-DIO-0066, Package=SOD323
D5: library part ATV-DIO-0048, Current="1.1mV @100mA", Forward Voltage="0.9V @ 10mA", Manufacturer 1=Nexperia, Package=SOD-123, Power=365mW, Temperature Range="-55 to +150°C", Tolerance=2.13%, Voltage=15V
D6: library part ATV-DIO-0038, Current=200mA, Forward Voltage="590mV @ If {}200mA", Manufacturer 1="Diodes Incorporated", Package=X1-DFN1006-2, Reverse Voltage=40V, Temperature Range="-65 to +150°C"
HOLE1 HOLE2 HOLE3 HOLE4 HOLE5 HOLE6: library part ATV-MISC-0013, Package="3.2mm Hole"
IC1: library part ATV-IC-0054, Manufacturer 1="Power Integrations", Package=InSOP-24D, Supply Voltage="4.65V to 5.15V", Temperature Range="-40 to +150°C"
IC2: library part ATV-IC-0048, Manufacturer 1=Nexperia, Output Current=100mA, Output Voltage=2.4-36V, Package=SOT-23, Supply Voltage="2.4v - 36V", Temperature Range="-40 to +125°C"
J1: library part ATV-MISC-0037, Manufacturer 1="METZ CONNECT USA Inc.", Temperature Range="-40 to +105°C"
J2: library part ATV-MISC-0036, Manufacturer 1="METZ CONNECT USA Inc.", Temperature Range="-40 to +105°C"
J3: library part ATV-MISC-0039, Manufacturer 1="TE Connectivity AMP Connectors", Temperature Range="-40°C ~ 105°C"
L1: library part ATV-IND-0018, Current=4.2A, Manufacturer 1=Coilcraft, Package=CD1479-ALD, Resistor=20mOhm, Temperature Range="-40 to +125°C"
L2: library part ATV-IND-0022, Package=1008
PM1 PM2 PM3 PM4: library part ATV-MISC-0007
Q1 Q2: library part ATV-FET-0017, Current=9.4A, Manufacturer 1=Diodes, Package=PowerDI5060-8, Power=1.3W, Resistor="17.5mOhm @ Vgs {} 20V / Id {} 9.4", Temperature Range="-55 to +150°C", Voltage=150V
Q3: library part ATV-FET-0028, Package=SOT-323-3
Q4: library part ATV-FET-0019, Current=400mA, Manufacturer 1=Nexperia, Package=SOT-23, Power=1.14W, Resistor="1.4Ohm @ 350mA, 4.5V", Temperature Range="-55 to +150°C", Voltage=30V
R1 R2: library part ATV-RES-0818, Package=1206
R3 R6: library part ATV-RES-0822, Manufacturer 1="ROHM Semiconductor", Package=1206, Power=0.5W, Temperature Range="-55 to +155°C", Tolerance=5%
R4 R5 R7 R8 R9 R10 R11 R13 R14 R15: library part ATV-RES-0823, Manufacturer 1="ROHM Semiconductor", Package=1206, Power=0.5W, Temperature Range="-55 to +155°C", Tolerance=5%
R12: library part ATV-RES-0752, Manufacturer 1=Bourns, Package=0402, Power=0.063W, Temperature Range="-55 to +155°C", Tolerance=5%, Voltage=50V
R16: library part ATV-RES-0753, Manufacturer 1="Stackpole Electronics Inc", Package=0603, Power=0.1W, Temperature Range="-55 to +155°C", Tolerance=5%
R17: library part ATV-RES-0740, Manufacturer 1=YAGEO, Package=0805, Power=0.125W, Temperature Range="-55 to +155°C", Tolerance=5%, Voltage=150V
R18 R19: library part ATV-RES-0824, Manufacturer 1=YAGEO, Package=1206, Power=0.25W, Temperature Range="-55 to +155°C", Tolerance=5%
R20: library part ATV-RES-0757, Manufacturer 1=Panasonic, Package=0402, Power=0.1W, Temperature Range="-55 to +155°C", Tolerance=1%, Voltage=50V
R21: library part ATV-RES-0743, Manufacturer 1=Panasonic, Package=0402, Power=0.1W, Temperature Range="-55 to +155°C", Tolerance=5%, Voltage=50V
R22: library part ATV-RES-0756, Manufacturer 1="Stackpole Electronics Inc", Package=0402, Power=0.063W, Temperature Range="-55 to +155°C", Tolerance=1%
R23: library part ATV-RES-0762, Manufacturer 1=YAGEO, Package=1206, Power=0.25W, Temperature Range="-55 to +155°C", Tolerance=1%, Voltage=200V
R24 R25: library part ATV-RES-0778, Manufacturer 1=Vishay, Package=1206, Power=0.25W, Temperature Range="-65 to +170°C", Tolerance=1%
R26 R27 R28 R31: library part ATV-RES-0765, Manufacturer 1=Panasonic, Package=1206, Power=0.25W, Temperature Range="-55 to +155°C", Tolerance=5%
R29: library part ATV-RES-0825, Manufacturer 1=Panasonic, Package=0402, Power=0.1W, Temperature Range="-55 to +155°C", Tolerance=5%
R30: library part ATV-RES-0760, Manufacturer 1=YAGEO, Package=0603, Power=0.1W, Temperature Range="-55 to +155°C", Tolerance=5%, Voltage=75V
R32: library part ATV-RES-0745, Manufacturer 1=YAGEO, Package=0402, Power=0.063W, Temperature Range="-55 to +155°C", Tolerance=5%, Voltage=50V
T1: library part ATV-TRF-0022, Manufacturer 1="Power Integrations", Output Voltage=15V, Package=ElQ30, Supply Voltage=30-1000V
TP1 TP2 TP3 TP4 TP5 TP6 TP7 TP8 TP9 TP10: library part ATV-MISC-0025, Manufacturer 1="UWE electronic", Package=N

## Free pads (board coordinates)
  round 0 hole 55.12 unplated: 1(9.87,1421.46) 1(1279.44,7.33) 1(1279.44,2907.93) 1(3605.69,2907.88) 1(3605.69,7.28) 1(4940.13,1421.52) 2(7.35,1500.2) 2(1200.7,7.33) 2(1200.7,2907.93) 2(3684.43,2907.88) 2(3684.43,7.28) 2(4942.65,1500.26)

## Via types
v1: diameter 32, hole 16, Top Layer to Bottom Layer, tented both sides, 845 vias
v2: diameter 32/32/32/32/32/32 (per signal layer), hole 16, Top Layer to Bottom Layer, tented both sides, 1 vias

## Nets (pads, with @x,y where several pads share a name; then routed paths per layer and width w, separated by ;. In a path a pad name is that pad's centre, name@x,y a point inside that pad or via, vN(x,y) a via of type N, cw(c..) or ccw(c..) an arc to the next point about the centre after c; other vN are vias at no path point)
"15VCC (+)": C25.1 C26.1 J3.2 L2.2 R23.2 R26.1 R27.1 R28.1 R31.1 TP7.1
  other v1: 4679.08,1052.27 4729.08,1052.27 4779.08,1052.27 4829.08,1052.27 4679.08,1102.27 4729.08,1102.27 4779.08,1102.27 4829.08,1102.27 4679.08,1257.73 4729.08,1257.73 4779.08,1257.73 4829.08,1257.73 4679.08,1307.73 4729.08,1307.73 4779.08,1307.73 4829.08,1307.73 4575.34,1588.4 4625.34,1588.4 4575.34,1638.4 4625.34,1638.4 4838.23,2019.68 4838.23,2072.18 4838.23,2124.68 4838.23,2177.18 4838.23,2229.68 4838.23,2282.18 4838.23,2334.68 4838.23,2387.18 4838.23,2439.68
"15VCC (-)": C24.2 C25.2 C26.2 C27.1 IC1.1 IC2.3 J3.1 Q4.S R24.2 R25.2 R30.2 TP8.1 | length 3188.3
  Top Layer w15: IC1.1@2280.5,2057.6 2280.5,2004.72 2324.85,1960.37 2343.73,1960.37 C24.2@2344.11,1960 v1(2390,1960) ; v1(4286.84,1212) 4357,1212 ; Q4.S@4521.94,2294.24 4487.16,2294.24 4480.76,2300.64 R30.2@4444.09,2300.64 4444.09,2231.67 4454.3,2221.46 IC2.3@4454.3,2082.47 4464.49,2072.28 C27.1@4565,2072.28
  Mid-Layer 4 w15: v1(2390,1960) 2565.62,1960 2754.86,2149.24 3615.88,2149.24 4286.84,1478.29 v1(4286.84,1212)
  other v1: 4438.93,1052.27 4488.93,1052.27 4538.93,1052.27 4438.93,1102.27 4488.93,1102.27 4538.93,1102.27 4438.93,1279.38 4488.93,1279.38 4538.93,1279.38 4438.93,1329.38 4488.93,1329.38 4538.93,1329.38 4438.93,1379.38 4488.93,1379.38 4538.93,1379.38 4454.3,1982.47 4454.3,2032.47 4445,2240 4495,2240 4545,2240
CHECK: J3.3 R32.1 TP6.1 | length 783.8
  Top Layer w10: J3.3@4476.22,1763.61 v1(4568.61,1763.61)
  Top Layer w15: R32.1@4373.1,2315.21 4373.1,1836.22 4445.71,1763.61 J3.3@4476.22,1763.61
  Bottom Layer w30: TP6.1@4490,1765 4491.01,1763.99 4568.23,1763.99 v1(4568.61,1763.61)
DRAIN: D3.A IC1.24 T1.1 TP9.1 | length 59.1
  Bottom Layer w30: TP9.1@1595.96,2034.96 v1@1654.98,2034.98
  other v1: 1655,2035
Dsnub1: D1.A D3.K
Dsnub2: D1.K R6.2
FWD: C15.2 IC1.7 R16.2 | length 204.3
  Top Layer w10: IC1.7@2280.5,2234.76 2314.76,2234.76 2355,2275 C15.2@2370,2275 2385,2275 2409,2299 R16.2@2458.18,2299
GND: C15.1 C17.2 C18.2 C19.2 C20.1 C21.2 C23.2 C24.1 IC1.2 Q1.S Q2.S Q3.D R18.2 R19.2 R20.1 R24.1 R25.1 TP4.1 | length 222.3
  Top Layer w15: IC1.2@2280.5,2087.13 2357.63,2087.13 C17.2@2364.11,2080.65 2364.67,2081.22 C20.1@2439.45,2081.22 R20.1@2499.91,2081.22
  other v1: 3447.73,755.96 3497.73,755.96 3547.73,755.96 3702.27,755.96 3752.27,755.96 3802.27,755.96 3852.27,755.96 3902.27,755.96 3952.27,755.96 4002.27,755.96 4157.27,755.96 4207.27,755.96 4257.27,755.96 4307.27,755.96 4357.27,755.96 4407.27,755.96 4457.27,755.96 3347.73,805.96 3397.73,805.96 3447.73,805.96 3497.73,805.96 3547.73,805.96 3702.27,805.96 3752.27,805.96 3802.27,805.96 3852.27,805.96 3902.27,805.96 3952.27,805.96 4002.27,805.96 4157.27,805.96 4207.27,805.96 4257.27,805.96 4307.27,805.96 4357.27,805.96 4407.27,805.96 4457.27,805.96 4145.46,1117.35 4195.46,1117.35 4145.46,1167.35 4195.46,1167.35 4145.46,1217.35 4195.46,1217.35 4145.46,1267.35 4195.46,1267.35 4145.46,1317.35 4195.46,1317.35 4145.46,1367.35 4195.46,1367.35 4145.46,1417.35 4195.46,1417.35 4314.6,1830 4314.6,1880 4314.6,1930 2633.53,1954.51 4314.6,1980 2668.89,1989.86 2704.24,2025.22 4314.6,2030 2344.11,2035.65 2384.11,2035.65 2424.11,2035.65 2464.11,2035.65 3898.48,2035.63 2739.6,2060.57 3863.13,2070.98 4314.6,2080 2774.95,2095.93 3827.77,2106.34 4314.6,2130 3792.42,2141.7 3757.06,2177.05 4314.6,2180 3721.71,2212.41 4314.6,2230 4314.6,2280 4314.6,2330 4314.6,2380 2350,2430 2390,2430 4314.6,2430 4314.6,2480 4314.6,2530 2314.6,2580 2364.6,2580 2414.6,2580 2464.6,2580 2514.6,2580 2564.6,2580 2614.6,2580 2664.6,2580 2714.6,2580 2764.6,2580 2814.6,2580 2864.6,2580 2914.6,2580 2964.6,2580 3014.6,2580 3064.6,2580 3114.6,2580 3164.6,2580 3214.6,2580 3264.6,2580 3314.6,2580 3364.6,2580 3414.6,2580 3464.6,2580 3514.6,2580 3564.6,2580 3614.6,2580 3664.6,2580 3714.6,2580 3764.6,2580 3814.6,2580 3864.6,2580 3914.6,2580 3964.6,2580 4014.6,2580 4064.6,2580 4114.6,2580 4164.6,2580 4214.6,2580 4264.6,2580 4314.6,2580
"HV+ (1000 V)": J1.1 J1.2 L1.4 R1.1 TP1.1
  other v1: 131,1301.03 176,1301.03 221,1301.03 266,1301.03 130.94,1346.88 175.94,1346.88 220.94,1346.88 265.94,1346.88
HV-: J2.1 J2.2 L1.1 R2.1 TP2.1
  other v1: 134.46,496.22 179.46,496.22 224.46,496.22 269.46,496.22 135,540 180,540 225,540 270,540
HV_TRF: C1.1 C4.1 C7.1 C10.1 L1.3 R1.2 R4.1 R7.1 R9.1 R11.1 R14.1 T1.3
NetC1_2: C1.2 C2.1
NetC2_2: C2.2 C3.1
NetC4_2: C4.2 C5.1
NetC5_2: C5.2 C6.1
NetC7_2: C7.2 C8.1
NetC8_2: C8.2 C9.1
NetC12_1: C12.1 C13.1 D2.K R12.1 | length 2757.4
  Top Layer w15: R12.1@1707.72,2445.17 1722.54,2460 v1(1750,2460)
  Top Layer w30: D2.K@1070.39,400 1070.39,482 1073.39,485 C12.1@1075,485 ; v1(1075,527.11) C12.1@1075,485 ; C13.1@1180,485 C12.1@1075,485
  Mid-Layer 4 w15: v1(1075,527.11) 1096.08,506.03 1135.62,506.03 1162.16,532.57 1162.16,652.16 1575,1065 1575,1685 1955,2065 1955,2300 1808.01,2446.99 1763.01,2446.99 v1(1750,2460)
NetC14_1: C14.1 IC1.14 R12.2 | length 166.8
  Top Layer w12: R12.2@1672.28,2445.17 1672.28,2408.72 C14.1@1690,2391 1695.97,2391 1734.1,2352.87 IC1.14@1779.5,2352.87
NetC16_2: C16.2 R18.1 R19.1
  other v1: 3953.17,1214.35 3975.17,1267.35 3953.17,1324.35
NetC17_1: C17.1 D5.A IC1.4 | length 274.9
  Top Layer w10: IC1.4@2280.5,2146.18 2316.18,2146.18 2322.65,2152.65 C17.1@2364.11,2152.65 2437.65,2152.65 2455.39,2170.39 D5.A@2545.37,2170.39
NetC20_2: C20.2 IC1.3 R20.2 R21.2 R22.1 | length 396.1
  Top Layer w10: IC1.3@2280.5,2116.65 C20.2@2439.45,2116.65 R20.2@2499.91,2116.65 2518.35,2116.65 2535,2100 2535,2065 2548.7,2051.3 R22.1@2568.82,2051.3 R21.2@2629,2051.3
NetC22_2: C22.2 R21.1 | length 48.5
  Top Layer w15: R21.1@2629,2086.73 2629.09,2086.82 C22.2@2629.09,2135.24
NetC27_2: C27.2 IC2.1 R29.2 | length 130.9
  Top Layer w15: IC2.1@4491.3,2164.47 4491.84,2165 R29.2@4564.57,2165 4565,2164.57 C27.2@4565,2107.72
NetD2_A: D2.A T1.6
  other v1: 1280,485 1325,485 1370,485 1280,525 1325,525 1370,525 1280,565 1325,565 1370,565
NetD4_K: D4.K Q1.G Q2.G Q3.S R17.1 | length 816.4
  Top Layer w15: v1(4047.99,1619.44) 4082.2,1619.44 4101.76,1599.89 Q3.S@4136.9,1599.89
  Top Layer w20: Q2.G@4047.99,1113.32 v1(4047.99,1162.23) ; Q1.G@4048.26,1570.27 Q1.G@4047.99,1570.53 v1(4047.99,1619.44) D4.K@4047.99,1673.67 4079.1,1673.67 4087.1,1681.67 R17.1@4154.48,1681.67
  Mid-Layer 4 w20: v1(4047.99,1162.23) v1(4047.99,1619.44)
NetD5_K: D5.K D6.K | length 129.6
  Top Layer w10: D5.K@2539.97,2305 D5.K@2545.37,2299.61 2610.39,2299.61 2629.09,2280.91 D6.K@2629.09,2250.39
NetQ4_D: Q4.D R26.2 R27.2 R28.2 R29.1 R31.2 | length 118.4
  Top Layer w15: Q4.D@4604.68,2331.64 4604.68,2373.22 4618.65,2387.18 R31.2@4675.73,2387.18
NetQ4_G: Q4.G R30.1 R32.2 | length 156.5
  Top Layer w15: R32.2@4373.1,2350.64 4385.1,2362.64 R30.1@4444.09,2362.64 4486.1,2362.64 4492.5,2369.04 Q4.G@4521.94,2369.04
NetR3_2: R3.2 R6.1
PGOOD: IC2.2 J3.4 TP5.1 | length 463.9
  Top Layer w10: J3.4@4476.22,1913.61 4568.61,1913.61 v1(4570,1915)
  Top Layer w15: IC2.2@4417.3,2164.47 4417.3,2123.29 4403.51,2109.5 4403.51,1955.81 4445.71,1913.61 J3.4@4476.22,1913.61
  Bottom Layer w30: TP5.1@4505,1915 v1(4570,1915)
